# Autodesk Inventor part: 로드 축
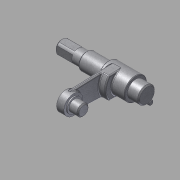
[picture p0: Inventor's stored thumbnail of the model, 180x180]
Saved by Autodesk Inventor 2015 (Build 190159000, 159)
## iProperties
Created: 2015-10
Part Number: 로드 축
Document SubType Name: Modeling
Designer: mdu
Density: 7.86 g/cm^3
Material: 강철, 연강
Mass: 157.936 g
Surface Area: 69.4484 cm^2
Volume: 20.0936 cm^3
Appearance: 금속-강(스테인리스, 브러시됨)
Author: mdu
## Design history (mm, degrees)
sketch "스케치1"
  geometry: L1 (-3.325, 13.5)-(-3.325, -13.5) reference; L2 (48.675, -15.7)-(48.675, 15.7) reference; L3 (48.675, 0)-(-26.325, 0); L4 (39.675, -18.06)-(39.675, 18.06) reference; L5 (15.675, 18.855)-(15.675, -18.855) reference; L6 (6.675, 15.7)-(6.675, -15.7) reference; L7 (3.675, -10)-(3.675, 10) reference; L8 (49.675, 7.5)-(39.675, 7.5); L9 (39.675, 7.5)-(39.675, 10); L10 (39.675, 10)-(15.675, 10); L11 (15.675, 10)-(15.675, 7.5); L12 (15.675, 7.5)-(-4.325, 7.5); L13 (-4.325, 7.5)-(-4.325, 6); L14 (-4.325, 6)-(-26.325, 6); L15 (-26.325, 6)-(-26.325, 0); L16 (48.675, 0)-(49.675, 0); L17 (49.675, 0)-(49.675, 7.5); 1 further point
  constraints: 22 end point, 7 perpendicular, 4 point on line, 2 parallel, 1 collinear, 1 midpoint
  dimensions: "d0" = 15 diameter of L8 L3; "d1" = 20 diameter of L10 L3; "d2" = 12 diameter of L14 L3; "d3" = 20 distance of L11.end L12.end; "d4" = 1 distance between parallel lines of L17 L2; "d5" = 75 distance of L3.start L3.end
revolve "회전1" sketch "스케치1" stored, may be unused: angle "d6" = 90 deg
chamfer "모따기1" distance "d7" = 1; stored, may be unused: second distance "d8" = 2, angle "d9" = 45 deg
node "작업 평면1"
sketch "스케치2"
  geometry: 1 further point
sketch "스케치3"
  geometry: L1 (9.993, -0.375)-(8.494, -40.319); L2 (-8.494, -40.319)-(-9.993, -0.375); C1 r 10 at (0, 0) reference; A1 r 8.5 centre (0, -40) between (8.494, -40.319) and (-8.494, -40.319); A2 r 10 centre (0, 0) between (-9.993, -0.375) and (9.993, -0.375) reference; 1 further point
  constraints: 4 end point, 4 point on circle, 4 tangent, 1 centre point, 1 vertical alignment
  dimensions: "d12" = 17 diameter of A1; "d22" = 40 distance of A1.centre A2.centre
  node "투영된 루프1"
extrude "돌출1" join sketch "스케치3" distance "d13" = 6.5; taper "d14" = 0 deg
node "작업 평면3"
  node "작업 평면2"
extrude "돌출2" join sketch "스케치3" stored distance "d17" = 6; taper "d18" = 0 deg
sketch "스케치7"
  geometry: L1 (-9.993, -0.375)-(-8.494, -40.319) reference; L2 (8.494, -40.319)-(9.993, -0.375) reference; A1 r 10 centre (0, 0) between (-9.993, -0.375) and (9.993, -0.375) reference; A2 r 15 centre (0, 0) between (-9.574, -11.547) and (9.574, -11.547); 1 further point
  constraints: 2 point on circle, 2 point on line, 1 centre point, 1 coincident
  dimensions: "d32" = 30 diameter of A2
extrude "돌출6" join sketch "스케치7" distance "d33" = 6; taper "d34" = 0 deg
sketch "스케치5"
  geometry: C1 r 5 at (0, 0) reference; C2 r 6.5 at (0, 0); 1 further point
  constraints: 1 centre point, 1 coincident
  dimensions: "d23" = 13 diameter of C2
  node "참조8"
extrude "돌출4" join sketch "스케치5" distance "d24" = 9; taper "d25" = 0 deg
extrude "돌출5" join sketch "스케치5" distance "d26" = 1; taper "d27" = 0 deg
fillet "모깎기1" dims "d28" = 1
chamfer "모따기2" distance "d29" = 1; stored, may be unused: second distance "d30" = 2, angle "d31" = 45 deg
chamfer "모따기3" distance "d35" = 0.5; stored, may be unused: second distance "d36" = 2, angle "d37" = 45 deg
sketch "스케치8"
  geometry: L1 (-3.25, 5.044)-(3.25, 5.044); L2 (5.044, 3.25)-(5.044, -3.25); L3 (3.25, -5.044)-(-3.25, -5.044); L4 (-5.044, -3.25)-(-5.044, 3.25); 2 further points
  constraints: 8 end point, 6 perpendicular, 1 horizontal, 9 other
  dimensions: "d38" = 6.5 distance of L3.start L3.end
extrude "돌출7" cut sketch "스케치8" distance "d39" = 15; taper "d40" = 0 deg
node "작업 평면4"
sketch "스케치9"
  geometry: L1 (7.66, 6.428)-(25.279, 21.212); L2 (23.973, 23.344)-(1.901, 9.818); L3 (27.152, 19.555)-(9.999, 0.167); L4 (28.659, 0)-(-16.444, 0) reference; C1 r 2 at (25.279, 21.212); A1 r 10 centre (0, 0) between (7.66, 6.428) and (1.901, 9.818) reference; A2 r 2.5 centre (25.279, 21.212) between (23.973, 23.344) and (27.152, 19.555); 1 further point
  constraints: 6 end point, 5 point on circle, 2 centre point, 2 coincident, 2 tangent, 1 point on line
  dimensions: "d42" = 23 distance of L1.start L1.end; "d43" = 5 diameter of A2; "d44" = 17 deg angle of L3 L2; "d45" = 8.5 deg angle of L1 L2 (= 0.5 x d44); "d46" = 40 deg angle of L4 L1; "d54" = 4 diameter of C1
extrude "돌출8" join sketch "스케치9" stored distance "d47" = 3; taper "d48" = 0 deg
extrude "돌출9" join sketch "스케치9" stored distance "d49" = 4; taper "d50" = 0 deg
fillet "모깎기2" dims "d51" = 1
fillet "모깎기3" dims "d52" = 1
fillet "모깎기4" dims "d53" = 1
extrude "돌출10" join sketch "스케치9" stored distance "d55" = 15; taper "d56" = 0 deg
chamfer "모따기4" distance "d57" = 0.5; stored, may be unused: second distance "d58" = 2, angle "d59" = 45 deg
node "솔리드1"
node "참조1"
node "참조2"
node "참조3"
node "참조4"
node "참조5"
node "참조6"
other parameters: "d10" = -8.5, "d15" = -1, "d16" = -3, "d41" = -15
